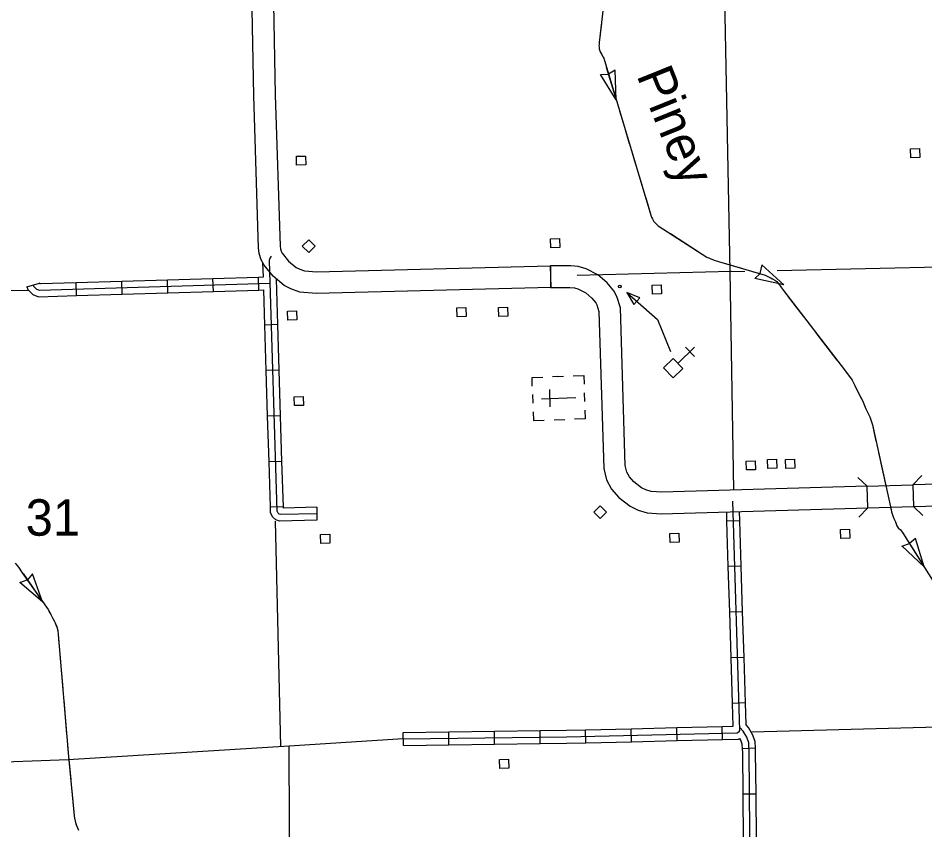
# Model space of a CAD drawing. Extents: x 1084508 to 1142749, y 1057638 to 1093403.
# Drawn here: x 1107089 to 1110384, y 1067118 to 1070069 of the extents above; entities that cross this region are included whole.
import ezdxf

# ---------------------------------------------------------------- set-up
doc = ezdxf.new("R2010")
doc.units = 0
for name, color, linetype in [('Level 10', 7, 'Continuous'), ('Level 32', 7, 'Continuous'), ('Level 35', 7, 'Continuous'), ('Level 37', 7, 'Continuous'), ('Level 4', 7, 'Continuous'), ('Level 43', 7, 'Continuous'), ('Level 5', 7, 'Continuous'), ('Level 56', 7, 'Continuous'), ('Level 57', 7, 'Continuous')]:
    doc.layers.add(name, color=color, linetype=linetype)

msp = doc.modelspace()

# ---------------------------------------------------------------- linework, layer by layer
at = {"layer": 'Level 10'}
for p, q in [((1109022.2, 1069168.4), (1109024.1, 1069089.9)), ((1109023.3, 1069168.4), (1109023, 1069089.9)), ((1110339.9, 1068371.8), (1110342.2, 1068293.3)), ((1110176.6, 1068288.5), (1110174.3, 1068366.9))]:
    msp.add_line(p, q, dxfattribs=at)
for points in [[(1109024.1, 1069089.9), (1108172.1, 1069068.4), (1108112.7, 1069072.2), (1108080.2, 1069084.3), (1108055.8, 1069097.1), (1108015.3, 1069130.6), (1107983.4, 1069170.6), (1107972.3, 1069190), (1107964.5, 1069213.7), (1107962.1, 1069234.3), (1107944.9, 1069787.9), (1107922.7, 1070978.9)], [(1108001.1, 1070980.2), (1108023.3, 1069789.8), (1108040.4, 1069240.1), (1108041.6, 1069230.6), (1108044.3, 1069222.1), (1108048.5, 1069214.9), (1108071.6, 1069185.9), (1108099.5, 1069162.7), (1108112.2, 1069156.1), (1108129.2, 1069149.8), (1108173.6, 1069147), (1109022.2, 1069168.4)], [(1110174.3, 1068366.9), (1109427.4, 1068345.1), (1109388.8, 1068348.4), (1109369.7, 1068354), (1109354.2, 1068361.4), (1109326, 1068382.9), (1109310.1, 1068401.6), (1109300.8, 1068418.8), (1109295.2, 1068442.3), (1109277.5, 1069016.1), (1109264.2, 1069057.5), (1109253.6, 1069078.1), (1109229, 1069106.8), (1109195.6, 1069135.2), (1109152.7, 1069158.1), (1109123.7, 1069166.2), (1109096.7, 1069168), (1109023.3, 1069168.4)], [(1109023, 1069089.9), (1109093.9, 1069089.6), (1109110.3, 1069088.5), (1109123.2, 1069084.8), (1109151.2, 1069069.9), (1109173.4, 1069051.1), (1109188.1, 1069033.9), (1109191.5, 1069027.3), (1109199.4, 1069002.7), (1109217, 1068432), (1109226.8, 1068390.6), (1109245, 1068357.1), (1109271.6, 1068325.7), (1109313, 1068294.1), (1109341.5, 1068280.4), (1109374.3, 1068270.8), (1109425.2, 1068266.5), (1110176.6, 1068288.5)], [(1110174.3, 1068366.9), (1110339.9, 1068371.8)], [(1111400.5, 1068113.9), (1111395.6, 1068146.1), (1111379.3, 1068196.8), (1111366.4, 1068222.7), (1111350.4, 1068242.8), (1111315.2, 1068292.5), (1111283, 1068324.8), (1111238.4, 1068352.6), (1111215.7, 1068363.3), (1111177.2, 1068375.3), (1111132.4, 1068381.1), (1111097.9, 1068383), (1110518.8, 1068377), (1110339.9, 1068371.8)], [(1110342.2, 1068293.3), (1110520.3, 1068298.5), (1111096.1, 1068304.5), (1111125.1, 1068303), (1111160.3, 1068298.4), (1111187.2, 1068289.9), (1111200.9, 1068283.6), (1111233.8, 1068263), (1111254.9, 1068241.8), (1111287.6, 1068195.7), (1111299.8, 1068180.3), (1111306.4, 1068167.1), (1111318.9, 1068128.1), (1111322.1, 1068107.1)], [(1110176.6, 1068288.5), (1110342.2, 1068293.3)]]:
    msp.add_lwpolyline(points, dxfattribs=at)
at = {"layer": 'Level 32'}
for p, q in [((1107963.8, 1069080.6), (1107962.4, 1069127.7)), ((1107120.7, 1069092.7), (1107165.9, 1069105.7)), ((1107301.2, 1069060.5), (1107299.8, 1069107.6)), ((1107466.8, 1069065.6), (1107465.4, 1069112.6)), ((1107632.5, 1069070.6), (1107631.1, 1069117.7)), ((1107798.2, 1069075.6), (1107796.7, 1069122.7)), ((1108032.5, 1068954.7), (1107985.4, 1068953.2)), ((1108037.5, 1068789), (1107990.5, 1068787.6)), ((1108042.6, 1068623.4), (1107995.5, 1068621.9)), ((1108047.6, 1068457.7), (1108000.6, 1068456.3)), ((1108052.7, 1068292.1), (1108005.6, 1068290.6)), ((1108173.7, 1068290.8), (1108174.8, 1068243.7)), ((1109711.5, 1068241.9), (1109664.5, 1068240.4)), ((1109716.6, 1068076.2), (1109669.5, 1068074.8)), ((1109721.6, 1067910.5), (1109674.5, 1067909.1)), ((1109726.7, 1067744.9), (1109679.6, 1067743.5)), ((1109731.7, 1067579.2), (1109684.6, 1067577.8)), ((1108985.8, 1067431.5), (1108985.2, 1067478.6)), ((1109151.8, 1067434.5), (1109150.7, 1067481.6)), ((1109317.5, 1067438.4), (1109316.3, 1067485.5)), ((1109483.1, 1067442.4), (1109482, 1067489.4)), ((1109648.8, 1067446.3), (1109647.7, 1067493.4)), ((1108488.7, 1067424.9), (1108488.1, 1067472)), ((1108654.4, 1067427.1), (1108653.8, 1067474.2)), ((1108820.1, 1067429.3), (1108819.5, 1067476.4)), ((1109768.2, 1067414.4), (1109721.2, 1067412.3)), ((1109770.1, 1067247.8), (1109723.1, 1067247.4))]:
    msp.add_line(p, q, dxfattribs=at)
for points in [[(1108174.2, 1068267.3), (1108041.6, 1068264), (1108037.2, 1068265.4), (1108033.6, 1068268.8), (1108029.6, 1068276.8), (1108001.8, 1069187.6), (1108003, 1069194), (1108009.3, 1069204.2)], [(1107980.1, 1069128.2), (1107978.5, 1069179.1)], [(1107796.7, 1069122.7), (1107962.4, 1069127.7)], [(1107962.4, 1069127.7), (1107980.1, 1069128.2)], [(1107120.7, 1069092.7), (1107123.5, 1069082.8), (1107142.2, 1069063.7), (1107162.6, 1069056.3), (1107301.2, 1069060.5)], [(1107143.3, 1069099.2), (1107144.5, 1069095), (1107155.2, 1069084), (1107166.4, 1069080), (1108003.5, 1069105.4)], [(1107165.5, 1069107.2), (1107168.3, 1069104.3), (1107170.1, 1069103.7), (1107299.8, 1069107.6)], [(1107299.8, 1069107.6), (1107465.4, 1069112.6)], [(1107465.4, 1069112.6), (1107631.1, 1069117.7)], [(1107631.1, 1069117.7), (1107796.7, 1069122.7)], [(1108032.5, 1068954.7), (1108027.4, 1069120.6)], [(1107301.2, 1069060.5), (1107466.8, 1069065.6)], [(1107466.8, 1069065.6), (1107632.5, 1069070.6)], [(1107632.5, 1069070.6), (1107798.2, 1069075.6)], [(1107798.2, 1069075.6), (1107963.8, 1069080.6)], [(1107963.8, 1069080.6), (1107981.5, 1069081.2)], [(1107985.4, 1068953.2), (1107981.5, 1069081.2)], [(1107990.5, 1068787.6), (1107985.4, 1068953.2)], [(1108037.5, 1068789), (1108032.5, 1068954.7)], [(1107995.5, 1068621.9), (1107990.5, 1068787.6)], [(1108042.6, 1068623.4), (1108037.5, 1068789)], [(1108000.6, 1068456.3), (1107995.5, 1068621.9)], [(1108047.6, 1068457.7), (1108042.6, 1068623.4)], [(1108005.6, 1068290.6), (1108000.6, 1068456.3)], [(1108052.7, 1068292.1), (1108047.6, 1068457.7)], [(1109081.3, 1067456.4), (1109701.1, 1067471.1), (1109709.1, 1067475.1), (1109711.2, 1067479.6), (1109685.8, 1068312.8)], [(1108174.8, 1068243.7), (1108038.3, 1068240.4), (1108025, 1068244.6), (1108014.5, 1068254.4), (1108006.2, 1068270.9), (1108005.6, 1068290.6)], [(1108173.7, 1068290.8), (1108052.8, 1068287.8), (1108052.7, 1068292.1)], [(1109664.5, 1068240.4), (1109663.5, 1068273.5)], [(1109711.5, 1068241.9), (1109710.5, 1068274.8)], [(1109669.5, 1068074.8), (1109664.5, 1068240.4)], [(1109716.6, 1068076.2), (1109711.5, 1068241.9)], [(1109674.5, 1067909.1), (1109669.5, 1068074.8)], [(1109721.6, 1067910.5), (1109716.6, 1068076.2)], [(1109679.6, 1067743.5), (1109674.5, 1067909.1)], [(1109726.7, 1067744.9), (1109721.6, 1067910.5)], [(1109684.6, 1067577.8), (1109679.6, 1067743.5)], [(1109731.7, 1067579.2), (1109726.7, 1067744.9)], [(1109647.7, 1067493.4), (1109687.2, 1067494.3), (1109684.6, 1067577.8)], [(1109734.1, 1067500.2), (1109731.7, 1067579.2)], [(1108819.5, 1067476.4), (1108985.2, 1067478.6)], [(1108985.2, 1067478.6), (1109080.9, 1067479.9), (1109150.7, 1067481.6)], [(1109150.7, 1067481.6), (1109316.3, 1067485.5)], [(1109316.3, 1067485.5), (1109482, 1067489.4)], [(1109482, 1067489.4), (1109647.7, 1067493.4)], [(1109756.3, 1066118.6), (1109745.3, 1067399.3), (1109743.8, 1067434.2), (1109736.5, 1067454.7), (1109723.2, 1067476.6), (1109711.4, 1067490.6)], [(1109768.2, 1067414.4), (1109767.2, 1067438.7), (1109757.9, 1067464.8), (1109742.4, 1067490.3), (1109734.1, 1067500.2)], [(1108488.1, 1067472), (1108653.8, 1067474.2)], [(1108488.4, 1067448.5), (1109081.3, 1067456.4)], [(1108653.8, 1067474.2), (1108819.5, 1067476.4)], [(1109483.1, 1067442.4), (1109648.8, 1067446.3)], [(1109648.8, 1067446.3), (1109707, 1067447.7), (1109711.7, 1067450.1)], [(1109721.2, 1067412.3), (1109720.4, 1067429.6), (1109715.1, 1067444.5), (1109711.7, 1067450.1)], [(1108488.7, 1067424.9), (1108654.4, 1067427.1)], [(1108654.4, 1067427.1), (1108820.1, 1067429.3)], [(1108820.1, 1067429.3), (1108985.8, 1067431.5)], [(1108985.8, 1067431.5), (1109081.7, 1067432.8), (1109151.8, 1067434.5)], [(1109151.8, 1067434.5), (1109317.5, 1067438.4)], [(1109317.5, 1067438.4), (1109483.1, 1067442.4)], [(1109723.1, 1067247.4), (1109721.8, 1067398.7), (1109721.2, 1067412.3)], [(1109770.1, 1067247.8), (1109768.8, 1067399.9), (1109768.2, 1067414.4)], [(1109724.5, 1067081.7), (1109723.1, 1067247.4)], [(1109771.6, 1067082.1), (1109770.1, 1067247.8)]]:
    msp.add_lwpolyline(points, dxfattribs=at)
at = {"layer": 'Level 37'}
for points in [[(1110339.9, 1068371.8), (1110372.2, 1068406)], [(1110140, 1068399.2), (1110174.3, 1068366.9)], [(1110176.6, 1068288.5), (1110144.3, 1068254.2)], [(1110376.5, 1068261), (1110342.2, 1068293.3)]]:
    msp.add_lwpolyline(points, dxfattribs=at)
at = {"layer": 'Level 4'}
for points in [[(1111334.9, 1067515.4), (1109754.8, 1067473.5)], [(1108488.4, 1067448.5), (1108073.8, 1067422.4), (1107270.2, 1067372.5), (1106284.4, 1067336.1)]]:
    msp.add_lwpolyline(points, dxfattribs=at)
at = {"layer": 'Level 43'}
for p, q in [((1109205.2, 1069863.9), (1109233.9, 1069864.8)), ((1109261.9, 1069772.3), (1109205.2, 1069863.9)), ((1109258.6, 1069879.9), (1109234.3, 1069864.9)), ((1109261.9, 1069772.3), (1109258.6, 1069879.9)), ((1109791.8, 1069172.5), (1109783.7, 1069140.3)), ((1109871.2, 1069099.8), (1109791.8, 1069172.5)), ((1109766, 1069123), (1109783.6, 1069139.9)), ((1109871.2, 1069099.8), (1109766, 1069123)), ((1110350, 1068177), (1110327.7, 1068159.1)), ((1110381.2, 1068074.2), (1110350.1, 1068177.4)), ((1110300.6, 1068149.8), (1110327.3, 1068158.7)), ((1110380.9, 1068073.8), (1110300.8, 1068149.2)), ((1107140.9, 1068048.7), (1107122.5, 1068026.8)), ((1107177.6, 1067947.4), (1107140.9, 1068048.7)), ((1107095.2, 1068016.8), (1107122.2, 1068026.6)), ((1107177.6, 1067947.4), (1107095.2, 1068016.8))]:
    msp.add_line(p, q, dxfattribs=at)
for points in [[(1109257.7, 1070481.8), (1109200.5, 1069980.4), (1109199.7, 1069975), (1109199, 1069969.9), (1109199.8, 1069964.3), (1109200.6, 1069957.7), (1109201.4, 1069953.6), (1109204.2, 1069946.5), (1109207.2, 1069940.3), (1109209.5, 1069936.3), (1109214.2, 1069927.3), (1109216.6, 1069923), (1109387.9, 1069352.9), (1109390.1, 1069345.7), (1109393.7, 1069339.6), (1109397.7, 1069332.5), (1109399.4, 1069329.4), (1109405.6, 1069322), (1109414.7, 1069314.2), (1109590.8, 1069200.3), (1109603.5, 1069195.4), (1109617.6, 1069189.3), (1109634.3, 1069184.8), (1109803, 1069134.3), (1109820.2, 1069126.1), (1109824, 1069124.3), (1109829.1, 1069121.6), (1109829.5, 1069120.7), (1109839.1, 1069116), (1109845.8, 1069111.2), (1109849.4, 1069106.9), (1109854.3, 1069101.1), (1109857.9, 1069096.2), (1109862.6, 1069088.5), (1109869.5, 1069079), (1110091.2, 1068790.1), (1110119.4, 1068752.7), (1110128.9, 1068733.8), (1110142.4, 1068705.9), (1110156.5, 1068679), (1110169.4, 1068649), (1110183.3, 1068619.8), (1110192.8, 1068590), (1110260.7, 1068281.6), (1110262.6, 1068274.1), (1110267.1, 1068260.1), (1110270.9, 1068249.9), (1110277, 1068237.5), (1110278.1, 1068233.8), (1110282.2, 1068222.9), (1110286.8, 1068216.1), (1110295.3, 1068208.2), (1110302.5, 1068198.7), (1110654.1, 1067640.4)], [(1109208.6, 1070051.3), (1109200.5, 1069980.4), (1109199.7, 1069975), (1109199, 1069969.9), (1109199.8, 1069964.3), (1109200.6, 1069957.7), (1109201.4, 1069953.6), (1109204.2, 1069946.5), (1109207.2, 1069940.3), (1109209.5, 1069936.3), (1109212.7, 1069930.3)], [(1109226.1, 1069891.3), (1109261.9, 1069772.3)], [(1109273.8, 1069732.6), (1109291.7, 1069673.1)], [(1109291.7, 1069673.1), (1109309.6, 1069613.5)], [(1109321.5, 1069573.9), (1109357.3, 1069454.8)], [(1109369.2, 1069415.2), (1109387.9, 1069352.9), (1109390.1, 1069345.7), (1109393.7, 1069339.6), (1109397.7, 1069332.5), (1109399.4, 1069329.4), (1109405.6, 1069322), (1109414.7, 1069314.2), (1109424.2, 1069308)], [(1109459, 1069285.5), (1109563.4, 1069218)], [(1109599, 1069197.1), (1109603.5, 1069195.4), (1109617.6, 1069189.3), (1109634.3, 1069184.8), (1109717.5, 1069159.9)], [(1109757.2, 1069148), (1109803, 1069134.3), (1109820.2, 1069126.1), (1109824, 1069124.3), (1109829.1, 1069121.6), (1109829.5, 1069120.7), (1109839.1, 1069116), (1109845.8, 1069111.2), (1109849.4, 1069106.9), (1109851.8, 1069104.1)], [(1109887.1, 1069056.1), (1109924.9, 1069006.8)], [(1109924.9, 1069006.8), (1109962.7, 1068957.5)], [(1109988, 1068924.6), (1110063.6, 1068826)], [(1110088.8, 1068793.1), (1110091.2, 1068790.1), (1110119.4, 1068752.7), (1110128.9, 1068733.8), (1110142.4, 1068705.9), (1110152.4, 1068686.9)], [(1110169.4, 1068649.1), (1110169.4, 1068649), (1110183.3, 1068619.8), (1110192.8, 1068590), (1110205.8, 1068530.9)], [(1110214.7, 1068490.4), (1110241.5, 1068369)], [(1110259.9, 1068285.6), (1110260.7, 1068281.6), (1110262.6, 1068274.1), (1110267.1, 1068260.1), (1110270.9, 1068249.9), (1110277, 1068237.5), (1110278.1, 1068233.8), (1110282.2, 1068222.9), (1110286.8, 1068216.1), (1110290.7, 1068212.5)], [(1110314.9, 1068179), (1110348, 1068126.4)], [(1110348, 1068126.4), (1110381.2, 1068073.8)], [(1107078.4, 1068088), (1107090.2, 1068073.4), (1107104, 1068052.8), (1107197.6, 1067918.8), (1107208, 1067900.3), (1107215, 1067886.4), (1107219.7, 1067878.4), (1107223.4, 1067871), (1107228.9, 1067856.4), (1107232.5, 1067842.1), (1107234.5, 1067828.1), (1107271.9, 1067384.8), (1107292.3, 1067168.5), (1107293.6, 1067159.8), (1107297.6, 1067144.2), (1107301.1, 1067133.3), (1107307.9, 1067116.6)], [(1107106.5, 1068049.3), (1107177.6, 1067947.4)], [(1107200.8, 1067913.1), (1107208, 1067900.3), (1107215, 1067886.4), (1107219.7, 1067878.4), (1107223.4, 1067871), (1107228.5, 1067857.6)], [(1107228.5, 1067857.6), (1107228.9, 1067856.4), (1107232.5, 1067842.1), (1107234.5, 1067828.1), (1107237.2, 1067796.2)], [(1107240.7, 1067754.9), (1107251.2, 1067631.1)], [(1107254.6, 1067589.8), (1107265.1, 1067465.9)], [(1107268.6, 1067424.7), (1107271.9, 1067384.8), (1107279.9, 1067300.9)], [(1107283.8, 1067259.6), (1107292.3, 1067168.5), (1107293.6, 1067159.8), (1107297.6, 1067144.2), (1107300, 1067136.7)]]:
    msp.add_lwpolyline(points, dxfattribs=at)
at = {"layer": 'Level 5'}
for points in [[(1109689.8, 1068352.7), (1109676.7, 1069147.6), (1109643.9, 1070823.4), (1109613.3, 1072450.6)], [(1109847.2, 1069151.4), (1110488.8, 1069165.7)], [(1109679.8, 1069147.6), (1109120.6, 1069133.5)], [(1109676.7, 1069147.6), (1109729.6, 1069148.7)], [(1107127.5, 1069078.7), (1106255.6, 1069073.6)], [(1108023.4, 1068240), (1108042.3, 1067420.5)], [(1108080.9, 1065698.7), (1108073.8, 1067422.4)]]:
    msp.add_lwpolyline(points, dxfattribs=at)
at = {"layer": 'Level 56'}
for points in [[(1110333, 1069561.2), (1110331.8, 1069593.9), (1110364.6, 1069595), (1110365.7, 1069562.4)], [(1110333, 1069561.2), (1110331.8, 1069593.9), (1110364.6, 1069595), (1110365.7, 1069562.4)], [(1108100.9, 1069534.1), (1108099.8, 1069566.7), (1108132.6, 1069567.8), (1108133.7, 1069535.2)], [(1108121.5, 1069240.3), (1108144.7, 1069263.3), (1108167.8, 1069240.1), (1108144.6, 1069217)], [(1109024.4, 1069233.7), (1109023.2, 1069266.4), (1109056, 1069267.5), (1109057.1, 1069234.9)], [(1109024.4, 1069233.7), (1109023.2, 1069266.4), (1109056, 1069267.5), (1109057.1, 1069234.9)], [(1109393.8, 1069065.7), (1109392.7, 1069098.3), (1109425.4, 1069099.4), (1109426.5, 1069066.8)], [(1108069, 1068970.7), (1108067.9, 1069003.4), (1108100.6, 1069004.5), (1108101.8, 1068971.9)], [(1108684, 1068983.4), (1108682.8, 1069016.1), (1108715.6, 1069017.2), (1108716.7, 1068984.5)], [(1108835.1, 1068984.8), (1108834, 1069017.5), (1108866.8, 1069018.6), (1108867.9, 1068986)], [(1108092.8, 1068660.1), (1108091.7, 1068692.7), (1108124.4, 1068693.8), (1108125.5, 1068661.2)], [(1109735.2, 1068426.2), (1109734.1, 1068458.9), (1109766.8, 1068460), (1109767.9, 1068427.4)], [(1109813.1, 1068431.4), (1109812, 1068464), (1109844.7, 1068465.2), (1109845.9, 1068432.5)], [(1109878.6, 1068432.2), (1109877.5, 1068464.9), (1109910.2, 1068466), (1109911.3, 1068433.4)], [(1109180.3, 1068273.2), (1109203.5, 1068296.2), (1109226.6, 1068273), (1109203.4, 1068249.9)], [(1109180.3, 1068273.2), (1109203.5, 1068296.2), (1109226.6, 1068273), (1109203.4, 1068249.9)], [(1110078.2, 1068177.7), (1110077.1, 1068210.3), (1110109.8, 1068211.5), (1110110.9, 1068178.8)], [(1110078.2, 1068177.7), (1110077.1, 1068210.3), (1110109.8, 1068211.5), (1110110.9, 1068178.8)], [(1108189.2, 1068158.8), (1108188.1, 1068191.5), (1108220.9, 1068192.6), (1108222, 1068160)], [(1109458.3, 1068162.7), (1109457.1, 1068195.3), (1109489.9, 1068196.5), (1109491, 1068163.8)], [(1109458.3, 1068162.7), (1109457.1, 1068195.3), (1109489.9, 1068196.5), (1109491, 1068163.8)], [(1108839.4, 1067341.5), (1108838.3, 1067374.1), (1108871, 1067375.2), (1108872.1, 1067342.6)]]:
    msp.add_lwpolyline(points, close=True, dxfattribs=at)
at = {"layer": 'Level 57'}
for p, q in [((1109546.8, 1068872.4), (1109486.3, 1068813.3)), ((1109513.5, 1068872.7), (1109546.4, 1068839.1)), ((1109050.2, 1068766.1), (1109030.9, 1068765.5)), ((1109050.2, 1068766.1), (1109070.1, 1068766.8)), ((1108958.2, 1068700.3), (1108959.3, 1068669)), ((1109022.6, 1068655.3), (1109020.4, 1068718.3)), ((1109147.5, 1068675.4), (1109146.5, 1068706.8)), ((1108990.2, 1068685.5), (1109115.6, 1068689.9)), ((1109052.9, 1068687.7), (1109052.9, 1068687.7)), ((1109052.9, 1068687.7), (1109052.9, 1068687.7)), ((1109036.3, 1068608.6), (1109075.5, 1068610))]:
    msp.add_line(p, q, dxfattribs=at)
for points in [[(1109301.2, 1069071.9), (1109412.5, 1068973.3), (1109459.7, 1068857.6)], [(1108957.2, 1068731.5), (1108956.1, 1068762.9), (1108995.3, 1068764.2)], [(1109105.1, 1068768), (1109144.3, 1068769.4), (1109145.4, 1068738)], [(1108960.4, 1068637.4), (1108961.5, 1068606), (1109000.7, 1068607.4)], [(1109148.6, 1068643.9), (1109149.7, 1068612.5), (1109110.5, 1068611.2)]]:
    msp.add_lwpolyline(points, dxfattribs=at)
for points in [[(1109326.5, 1069028.1), (1109347.8, 1069052.1), (1109301.2, 1069071.9)], [(1109433.5, 1068797.3), (1109468.5, 1068831.5), (1109504, 1068795.2), (1109469, 1068760.9)]]:
    msp.add_lwpolyline(points, close=True, dxfattribs=at)
msp.add_circle((1109275.5, 1069093.3), 4.71, dxfattribs=at)

# ---------------------------------------------------------------- texts
at = {"layer": 'Level 35'}
msp.add_text('Piney', height=132.58, rotation=291.9589, dxfattribs=at).set_placement((1109334.6, 1069861.6))
at = {"layer": 'Level 5'}
msp.add_text('31', height=132.58, dxfattribs=at).set_placement((1107116.2, 1068187.3))

doc.saveas('drawing.dxf')
